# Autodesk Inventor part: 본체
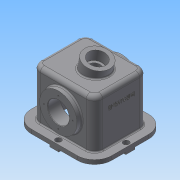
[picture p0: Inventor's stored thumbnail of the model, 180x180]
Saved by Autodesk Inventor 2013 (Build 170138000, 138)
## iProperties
Created: 2014-11
Part Number: 본체
Material: 알루미늄 6061
Document SubType Name: Modeling
Designer: Administrator
Density: 2.71 g/cm^3
Mass: 2881.87 g
Surface Area: 2079.03 cm^2
Volume: 1063.42 cm^3
Author: Administrator
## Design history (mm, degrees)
sketch "스케치1"
  geometry: L1 (-76, -65)-(76, -65); L2 (76, -65)-(76, 65); L3 (76, 65)-(-76, 65); L4 (-76, 65)-(-76, -65); L5 (-76, -65)-(76, 65); L6 (76, -65)-(-76, 65); L7 (-98, -87)-(98, -87); L8 (98, -87)-(98, 87); L9 (98, 87)-(-98, 87); L10 (-98, 87)-(-98, -87); L11 (-98, -87)-(98, 87); L12 (98, -87)-(-98, 87); 1 further point
  constraints: 24 end point, 4 midpoint, 4 parallel, 2 horizontal, 2 perpendicular
  dimensions: "d0" = 152 distance of L3.end L2.end; "d1" = 130 distance of L2.end L1.end; "d2" = 196 distance of L9.end L8.end; "d3" = 174 distance of L8.end L7.end
extrude "돌출1" new body sketch "스케치1" distance "d4" = 128; taper "d5" = 0 deg
sketch "스케치2"
  geometry: L1 (76, 128)-(-76, 128) reference; L2 (-98, 0)-(98, 0) reference; L3 (0, 68)-(-17.88, 152.121); L4 (0, 68)-(-62.657, 68); L5 (12.442, 158.566)-(20.759, 119.44); L6 (12.442, 158.566)-(-17.88, 152.121); L7 (20.759, 119.44)-(-9.564, 112.995); C1 r 45.5 at (0, 68); 2 further points
  constraints: 10 end point, 2 parallel, 1 centre point, 1 midpoint, 1 perpendicular, 1 point on line, 1 vertical alignment
  dimensions: "d6" = 91 diameter of C1; "d7" = 68 distance from line of L3.start L2; "d13" = 78 deg angle of L3 L4; "d14" = 86 distance of L3.end L3.start; "d15" = 62 diameter of L5 L3; "d67" = 40 distance between parallel lines of L7 L6
extrude "돌출2" join sketch "스케치2" stored distance "d8" = 154; taper "d9" = 0 deg
extrude "돌출3" join sketch "스케치1" distance "d11" = 10; taper "d12" = 0 deg
revolve "회전1" stored, may be unused: angle "d20" = 90 deg
sketch "스케치3"
  geometry: L1 (-76, 10)-(-76, 128) reference; L2 (76, 10)-(76, 128) reference; L3 (66, 0)-(66, 118); L4 (76, 128)-(-76, 128) reference; L5 (66, 118)-(-66, 118); L6 (-66, 0)-(-66, 118); L7 (-98, 0)-(98, 0) reference
  constraints: 6 end point, 3 parallel, 2 point on line
  dimensions: "d21" = 10 distance between parallel lines of L4 L5; "d22" = 10 distance between parallel lines of L2 L3; "d23" = 10 distance between parallel lines of L1 L6
extrude "돌출4" cut sketch "스케치3" stored distance "d24" = 110; taper "d25" = 0 deg
sketch "스케치4" dims "d27" = 70
  geometry: C1 r 45.5 at (0, 0) reference; C2 r 26 at (0, 0); 3 further points
  constraints: 2 coincident, 2 vertical alignment, 1 centre point, 2 other
  dimensions: "d26" = 52 diameter of C2
hole "구멍1" sketch "스케치4" diameter "d28" = 3.242; stored, may be unused: countersink angle "d32" = 90 deg, drill point angle "d34" = 118 deg; dims "d29" = 13, "d30" = 4, "d31" = 2, "d33" = 16
node "작업 평면1"
sketch "스케치5"
  geometry: L1 (-66, -55)-(66, -55) reference; L2 (66, -55)-(66, 55) reference; L3 (66, 55)-(-66, 55) reference; L4 (-66, 55)-(-66, -55) reference; L5 (-98, -87)-(98, -87) reference; L6 (-98, 87)-(-98, -87) reference; L7 (98, 87)-(-98, 87) reference; L8 (98, -87)-(98, 87) reference; L9 (0, 55)-(0, 45); L10 (45.5, 55)-(35.5, 45); L11 (35.5, 45)-(0, 45); 1 further point
  constraints: 6 end point, 1 midpoint, 1 parallel, 1 perpendicular, 1 point on line
  dimensions: "d39" = 10 distance between parallel lines of L11 L3; "d40" = 91 diameter of L10.start L9; "d41" = 71 diameter of L10.end L9
revolve "회전2" sketch "스케치5" stored, may be unused: angle "d42" = 90 deg
extrude "돌출5" cut sketch "스케치4" stored distance "d43" = 110; taper "d44" = 0 deg
sketch "스케치6"
  geometry: L1 (98, -87)-(-98, -87) reference; L2 (98, 87)-(98, -87) reference; L3 (-98, 87)-(98, 87) reference; L4 (-98, -87)-(-98, 87) reference; L5 (-11, -67)-(11, -67); L6 (11, -67)-(11, -87); L7 (11, -87)-(-11, -87); L8 (-11, -87)-(-11, -67); L9 (78, 11)-(98, 11); L10 (98, 11)-(98, -11); L11 (98, -11)-(78, -11); L12 (78, -11)-(78, 11); L13 (-11, 87)-(11, 87); L14 (11, 87)-(11, 67); L15 (11, 67)-(-11, 67); L16 (-11, 67)-(-11, 87); L17 (-98, -11)-(-78, -11); L18 (-78, -11)-(-78, 11); L19 (-78, 11)-(-98, 11); L20 (-98, 11)-(-98, -11); 14 further points
  constraints: 32 end point, 13 midpoint, 8 parallel, 7 coincident, 4 horizontal, 4 perpendicular, 1 vertical alignment
  dimensions: "d45" = 22 distance of L5.start L5.end; "d47" = 20 distance of L5.end L6.end; "d48" = 20 distance of L9.start L9.end; "d49" = 22 distance of L11.end L9.start; "d50" = 20 distance of L13.end L14.end; "d51" = 22 distance of L14.end L15.end; "d52" = 20 distance of L18.end L19.end; "d53" = 22 distance of L17.end L18.end
extrude "돌출6" join sketch "스케치6" distance "d54" = 5; taper "d55" = 0 deg
sketch "스케치7"
  geometry: L1 (-98, -87)-(98, -87) reference; L2 (98, -87)-(98, 87) reference; L3 (98, 87)-(-98, 87) reference; L4 (-98, 87)-(-98, -87) reference; L5 (-98, 0)-(98, 0); L6 (0, 87)-(0, -87); 5 further points
  constraints: 4 end point, 4 midpoint, 4 point on line
  dimensions: "d56" = 10 distance from line of point (0, 77) L3; "d57" = 10 distance from line of L4 point (-88, 0); "d58" = 10 distance of L6.end point (0, -77); "d59" = 10 distance from line of L2 point (88, 0)
hole "구멍2" sketch "스케치7" at (0, 77), (-88, 0), (88, 0), (0, -77) diameter "d60" = 9; stored, may be unused: countersink angle "d64" = 90 deg, drill point angle "d66" = 118 deg; dims "d61" = 13, "d62" = 14, "d63" = 8.6, "d65" = 16
hole "구멍3" diameter "d70" = 30; stored, may be unused: countersink angle "d74" = 90 deg, drill point angle "d76" = 118 deg; dims "d68" = 10, "d69" = 10, "d71" = 13, "d72" = 42, "d73" = 25, "d75" = 16
fillet "모깎기1" dims "d77" = 42, "d78" = 20, "d79" = 10
fillet "모깎기2" dims "d80" = 10, "d81" = 3
fillet "모깎기3" dims "d82" = 0.3
chamfer "모따기1" distance "d83" = 1; stored, may be unused: second distance "d84" = 2, angle "d85" = 45 deg
sketch "스케치9"
  geometry: L1 (-105, 0)-(-105, 90) reference; L2 (13, 0)-(13, 34) reference; 3 further points
  constraints: 1 horizontal alignment, 1 midpoint, 1 other
  dimensions: "d86" = 92 distance from line of L2 point (-79, 45)
feature "엠보싱1" sketch "스케치9" dims "d0" = 152, "d1" = 130, "d87" = 1, "d88" = 0
node "솔리드1"
pattern_circular "원형 패턴1" dims angle "d36" = 360 deg
mirror "대칭1"
mirror "대칭2"
node "투영된 루프1"
other parameters: "d38" = -68
